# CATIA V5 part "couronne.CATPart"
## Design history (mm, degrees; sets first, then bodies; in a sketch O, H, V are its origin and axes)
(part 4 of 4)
    point P2044 (31.6793, -36.3337)
    point P2045 (31.9191, -36.4708)
    point P2046 (31.9191, -36.4708)
    point P2047 (32.1734, -36.6103)
    point P2048 (32.1734, -36.6103)
    point P2049 (32.4425, -36.7519)
    point P2050 (32.4425, -36.7519)
    point P2051 (32.7264, -36.895)
    point P2052 (32.7264, -36.895)
    point P2053 (33.0253, -37.0391)
    point P2054 (33.0253, -37.0391)
    point P2055 (33.3393, -37.1839)
    point P2056 (33.3393, -37.1839)
    point P2057 (33.4796, -37.2456)
    point P2058 (33.4796, -37.2456)
    point P2059 (33.4958, -37.2509)
    point P2060 (33.4958, -37.2509)
    point P2061 (33.5874, -37.2626)
    point P2062 (33.5874, -37.2626)
    point P2063 (33.8133, -37.2056)
    point P2064 (33.8133, -37.2056)
    point P2069 (34.1759, -36.8016)
    point P2070 (34.1759, -36.8016)
    point P2071 (34.1938, -36.6479)
    point P2072 (34.1938, -36.6479)
    point P2073 (34.1867, -36.6005)
    point P2074 (34.1867, -36.6005)
    point P2075 (34.179, -36.5767)
    point P2076 (34.179, -36.5767)
    point P2077 (34.0784, -36.2886)
    point P2078 (34.0784, -36.2886)
    point P2079 (33.9611, -35.9708)
    point P2080 (33.9611, -35.9708)
    point P2081 (33.8434, -35.6679)
    point P2082 (33.8434, -35.6679)
    point P2083 (33.7256, -35.3801)
    point P2084 (33.7256, -35.3801)
    point P2085 (33.6083, -35.1072)
    point P2086 (33.6083, -35.1072)
    point P2087 (33.492, -34.849)
    point P2088 (33.492, -34.849)
    point P2089 (33.3772, -34.6055)
    point P2090 (33.3772, -34.6055)
    point P2091 (33.2643, -34.3765)
    point P2092 (33.2643, -34.3765)
    point P2093 (33.1537, -34.1618)
    point P2094 (33.1537, -34.1618)
    point P2095 (33.046, -33.9614)
    point P2096 (33.046, -33.9614)
    point P2101 (33.8665, -32.9934)
    point P2102 (33.8665, -32.9934)
    point P2103 (34.0598, -33.0995)
    point P2104 (34.0598, -33.0995)
    point P2105 (34.2674, -33.2087)
    point P2106 (34.2674, -33.2087)
    point P2107 (34.4892, -33.3205)
    point P2108 (34.4892, -33.3205)
    point P2109 (34.7254, -33.4344)
    point P2110 (34.7254, -33.4344)
    point P2111 (34.9762, -33.55)
    point P2112 (34.9762, -33.55)
    point P2113 (35.2418, -33.6669)
    point P2114 (35.2418, -33.6669)
    point P2115 (35.5222, -33.7845)
    point P2116 (35.5222, -33.7845)
    point P2117 (35.8175, -33.9023)
    point P2118 (35.8175, -33.9023)
    point P2119 (36.1278, -34.0199)
    point P2120 (36.1278, -34.0199)
    point P2121 (36.4532, -34.1367)
    point P2122 (36.4532, -34.1367)
    point P2123 (36.5984, -34.186)
    point P2124 (36.5984, -34.186)
    point P2125 (36.6149, -34.1898)
    point P2126 (36.6149, -34.1898)
    point P2127 (36.7073, -34.1935)
    point P2128 (36.7073, -34.1935)
    point P2129 (36.9273, -34.117)
    point P2130 (36.9273, -34.117)
    point P2135 (37.2533, -33.6829)
    point P2136 (37.2533, -33.6829)
    point P2137 (37.2577, -33.5283)
    point P2138 (37.2577, -33.5283)
    point P2139 (37.2465, -33.4817)
    point P2140 (37.2465, -33.4817)
    point P2141 (37.2368, -33.4586)
    point P2142 (37.2368, -33.4586)
    point P2143 (37.1115, -33.1804)
    point P2144 (37.1115, -33.1804)
    point P2145 (36.967, -32.874)
    point P2146 (36.967, -32.874)
    point P2147 (36.8233, -32.5826)
    point P2148 (36.8233, -32.5826)
    point P2149 (36.6809, -32.3061)
    point P2150 (36.6809, -32.3061)
    point P2151 (36.5402, -32.0444)
    point P2152 (36.5402, -32.0444)
    point P2153 (36.4019, -31.7974)
    point P2154 (36.4019, -31.7974)
    point P2155 (36.2662, -31.5648)
    point P2156 (36.2662, -31.5648)
    point P2157 (36.1338, -31.3465)
    point P2158 (36.1338, -31.3465)
    point P2159 (36.005, -31.1423)
    point P2160 (36.005, -31.1423)
    point P2161 (35.8802, -30.952)
    point P2162 (35.8802, -30.952)
    point P2167 (36.6132, -29.9162)
    point P2168 (36.6132, -29.9162)
    point P2169 (36.815, -30.005)
    point P2170 (36.815, -30.005)
    point P2171 (37.0313, -30.0957)
    point P2172 (37.0313, -30.0957)
    point P2173 (37.262, -30.1877)
    point P2174 (37.262, -30.1877)
    point P2175 (37.5073, -30.2807)
    point P2176 (37.5073, -30.2807)
    point P2177 (37.7672, -30.374)
    point P2178 (37.7672, -30.374)
    point P2179 (38.0419, -30.4673)
    point P2180 (38.0419, -30.4673)
    point P2181 (38.3315, -30.5599)
    point P2182 (38.3315, -30.5599)
    point P2183 (38.636, -30.6516)
    point P2184 (38.636, -30.6516)
    point P2185 (38.9553, -30.7417)
    point P2186 (38.9553, -30.7417)
    point P2187 (39.2897, -30.8297)
    point P2188 (39.2897, -30.8297)
    point P2189 (39.4386, -30.8661)
    point P2190 (39.4386, -30.8661)
    point P2191 (39.4554, -30.8685)
    point P2192 (39.4554, -30.8685)
    point P2193 (39.5478, -30.8641)
    point P2194 (39.5478, -30.8641)
    point P2195 (39.7603, -30.7687)
    point P2196 (39.7603, -30.7687)
    point P2201 (40.0472, -30.3079)
    point P2202 (40.0472, -30.3079)
    point P2203 (40.0381, -30.1534)
    point P2204 (40.0381, -30.1534)
    point P2205 (40.0229, -30.108)
    point P2206 (40.0229, -30.108)
    point P2207 (40.0112, -30.0859)
    point P2208 (40.0112, -30.0859)
    point P2209 (39.8621, -29.8197)
    point P2210 (39.8621, -29.8197)
    point P2211 (39.6914, -29.527)
    point P2212 (39.6914, -29.527)
    point P2213 (39.5229, -29.2492)
    point P2214 (39.5229, -29.2492)
    point P2215 (39.3569, -28.9862)
    point P2216 (39.3569, -28.9862)
    point P2217 (39.1941, -28.7378)
    point P2218 (39.1941, -28.7378)
    point P2219 (39.0347, -28.5037)
    point P2220 (39.0347, -28.5037)
    point P2221 (38.8793, -28.2838)
    point P2222 (38.8793, -28.2838)
    point P2223 (38.7283, -28.0779)
    point P2224 (38.7283, -28.0779)
    point P2225 (38.5822, -27.8857)
    point P2226 (38.5822, -27.8857)
    point P2227 (38.4413, -27.7071)
    point P2228 (38.4413, -27.7071)
    point P2233 (39.0812, -26.6113)
    point P2234 (39.0812, -26.6113)
    point P2235 (39.2901, -26.6822)
    point P2236 (39.2901, -26.6822)
    point P2237 (39.5134, -26.7537)
    point P2238 (39.5134, -26.7537)
    point P2239 (39.7512, -26.8253)
    point P2240 (39.7512, -26.8253)
    point P2241 (40.0037, -26.8965)
    point P2242 (40.0037, -26.8965)
    point P2243 (40.2708, -26.9668)
    point P2244 (40.2708, -26.9668)
    point P2245 (40.5526, -27.0357)
    point P2246 (40.5526, -27.0357)
    point P2247 (40.8491, -27.1028)
    point P2248 (40.8491, -27.1028)
    point P2249 (41.1604, -27.1676)
    point P2250 (41.1604, -27.1676)
    point P2251 (41.4864, -27.2295)
    point P2252 (41.4864, -27.2295)
    point P2253 (41.8272, -27.288)
    point P2254 (41.8272, -27.288)
    point P2255 (41.9787, -27.3114)
    point P2256 (41.9787, -27.3114)
    point P2257 (41.9957, -27.3122)
    point P2258 (41.9957, -27.3122)
    point P2259 (42.0873, -27.2999)
    point P2260 (42.0873, -27.2999)
    point P2261 (42.2906, -27.1863)
    point P2262 (42.2906, -27.1863)
    point P2267 (42.5363, -26.7022)
    point P2268 (42.5363, -26.7022)
    point P2269 (42.5138, -26.5491)
    point P2270 (42.5138, -26.5491)
    point P2271 (42.4947, -26.5052)
    point P2272 (42.4947, -26.5052)
    point P2273 (42.4811, -26.4842)
    point P2274 (42.4811, -26.4842)
    point P2275 (42.3094, -26.232)
    point P2276 (42.3094, -26.232)
    point P2277 (42.1138, -25.9553)
    point P2278 (42.1138, -25.9553)
    point P2279 (41.9217, -25.6933)
    point P2280 (41.9217, -25.6933)
    point P2281 (41.7335, -25.4457)
    point P2282 (41.7335, -25.4457)
    point P2283 (41.5496, -25.2124)
    point P2284 (41.5496, -25.2124)
    point P2285 (41.3704, -24.9932)
    point P2286 (41.3704, -24.9932)
    point P2287 (41.1964, -24.7877)
    point P2288 (41.1964, -24.7877)
    point P2289 (41.0281, -24.5957)
    point P2290 (41.0281, -24.5957)
    point P2291 (40.8658, -24.417)
    point P2292 (40.8658, -24.417)
    point P2293 (40.7099, -24.2513)
    point P2294 (40.7099, -24.2513)
    point P2299 (41.2518, -23.1039)
    point P2300 (41.2518, -23.1039)
    point P2301 (41.4661, -23.1563)
    point P2302 (41.4661, -23.1563)
    point P2303 (41.6948, -23.2081)
    point P2304 (41.6948, -23.2081)
    point P2305 (41.9379, -23.2586)
    point P2306 (41.9379, -23.2586)
    point P2307 (42.1956, -23.3076)
    point P2308 (42.1956, -23.3076)
    point P2309 (42.4678, -23.3543)
    point P2310 (42.4678, -23.3543)
    point P2311 (42.7546, -23.3985)
    point P2312 (42.7546, -23.3985)
    point P2313 (43.0558, -23.4395)
    point P2314 (43.0558, -23.4395)
    point P2315 (43.3716, -23.4768)
    point P2316 (43.3716, -23.4768)
    point P2317 (43.7018, -23.5101)
    point P2318 (43.7018, -23.5101)
    point P2319 (44.0463, -23.5387)
    point P2320 (44.0463, -23.5387)
    point P2321 (44.1993, -23.5487)
    point P2322 (44.1993, -23.5487)
    point P2323 (44.2163, -23.5481)
    point P2324 (44.2163, -23.5481)
    point P2325 (44.3064, -23.5278)
    point P2326 (44.3064, -23.5278)
    point P2327 (44.4992, -23.397)
    point P2328 (44.4992, -23.397)
    point P2329 (44.5566, -23.3139)
    point P2330 (44.5566, -23.3139)
    point P2333 (44.7017, -22.8933)
    point P2334 (44.7017, -22.8933)
    point P2335 (44.666, -22.7428)
    point P2336 (44.666, -22.7428)
    point P2337 (44.6431, -22.7007)
    point P2338 (44.6431, -22.7007)
    point P2339 (44.6277, -22.6809)
    point P2340 (44.6277, -22.6809)
    point P2341 (44.4347, -22.4447)
    point P2342 (44.4347, -22.4447)
    point P2343 (44.2157, -22.1861)
    point P2344 (44.2157, -22.1861)
    point P2345 (44.0015, -21.9418)
    point P2346 (44.0015, -21.9418)
    point P2347 (43.7924, -21.7116)
    point P2348 (43.7924, -21.7116)
    point P2349 (43.5889, -21.4952)
    point P2350 (43.5889, -21.4952)
    point P2351 (43.3913, -21.2924)
    point P2352 (43.3913, -21.2924)
    point P2353 (43.2001, -21.1028)
    point P2354 (43.2001, -21.1028)
    point P2355 (43.0156, -20.9263)
    point P2356 (43.0156, -20.9263)
    point P2357 (42.8383, -20.7624)
    point P2358 (42.8383, -20.7624)
    point P2359 (42.6686, -20.6109)
    point P2360 (42.6686, -20.6109)
    point P2363 (43.0768, -19.4152)
    point P2364 (43.0768, -19.4152)
    point P2365 (43.1085, -19.4206)
    point P2366 (43.1085, -19.4206)
    point P2367 (43.3265, -19.4542)
    point P2368 (43.3265, -19.4542)
    point P2369 (43.5588, -19.4858)
    point P2370 (43.5588, -19.4858)
    point P2371 (43.8055, -19.515)
    point P2372 (43.8055, -19.515)
    point P2373 (44.0664, -19.5413)
    point P2374 (44.0664, -19.5413)
    point P2375 (44.3417, -19.5642)
    point P2376 (44.3417, -19.5642)
    point P2377 (44.6312, -19.5831)
    line L829 (-62.9973, -0.5786) -> (-47.248, -0.434)
    reference projected line E1 (-12.4995, -0.1148) -> (-68.4352, -0.6286) from DatumCurve1
    line L830 (62.9973, 0.5786) -> (47.248, 0.434)
    reference projected line E2 (65.9972, 0.6062) -> (12.4995, 0.1148) from edge of DatumCurve2
    coincidence: E1 L829, L830 E2, P2 P2377, P3 P4, P5 P6, P7 P8, P9 P10, P11 P12, P13 P14, P15 P16, P17 P18, P23 P24, P25 P26, P27 P28, P29 P30, P31 P32, P33 P34, P35 P36, P37 P38, P39 P40, P41 P42, P43 P44, P45 P46, P47 P48, P49 P50, P55 P56, P57 P58, P59 P60, P61 P62, P63 P64, P65 P66, P67 P68, P69 P70, P71 P72, P73 P74, P75 P76, P77 P78, P79 P80, P81 P82, P83 P84, P89 P90, P91 P92, P93 P94, P95 P96, P97 P98, P99 P100, P101 P102, P103 P104, P105 P106, P107 P108, P109 P110, P111 P112, P113 P114, P115 P116, P121 P122, P123 P124, P125 P126, P127 P128, P129 P130, P131 P132, P133 P134, P135 P136, P137 P138, P139 P140, P141 P142, P143 P144, P145 P146, P147 P148, P149 P150, P155 P156, P157 P158, P159 P160, P161 P162, P163 P164, P165 P166, P167 P168, P169 P170, P171 P172, P173 P174, P175 P176, P177 P178, P179 P180, P181 P182, P187 P188, P189 P190, P191 P192, P193 P194, P195 P196, P197 P198, P199 P200, P201 P202, P203 P204, P205 P206, P207 P208, P209 P210, P211 P212, P213 P214, P215 P216, P221 P222, P223 P224, P225 P226, P227 P228, P229 P230, P231 P232, P233 P234, P235 P236, P237 P238, P239 P240, P241 P242, P243 P244, P245 P246, P247 P248, P253 P254, P255 P256, P257 P258, P259 P260, P261 P262, P263 P264, P265 P266, P267 P268, P269 P270, P271 P272, P273 P274, P275 P276, P277 P278, P279 P280, P281 P282, P287 P288, P289 P290, P291 P292, P293 P294, P295 P296, P297 P298, P299 P300, P301 P302, P303 P304, P305 P306, P307 P308, P309 P310, P311 P312, P313 P314, P319 P320, P321 P322, P323 P324, P325 P326, P327 P328, P329 P330, P331 P332, P333 P334, P335 P336, P337 P338, P339 P340, P341 P342, P343 P344, P345 P346, P347 P348, P353 P354, P355 P356, P357 P358, P359 P360, P361 P362, P363 P364, P365 P366, P367 P368, P369 P370, P371 P372, P373 P374, P375 P376, P377 P378, P379 P380, P385 P386, P387 P388, P389 P390, P391 P392, P393 P394, P395 P396, P397 P398, P399 P400, P401 P402, P403 P404, P405 P406, P407 P408, P409 P410, P411 P412, P413 P414, P419 P420, P421 P422, P423 P424, P425 P426, P427 P428, P429 P430, P431 P432, P433 P434, P435 P436, P437 P438, P439 P440, P441 P442, P443 P444, P445 P446, P451 P452, P453 P454, P455 P456, P457 P458, P459 P460, P461 P462, P463 P464, P465 P466, P467 P468, P469 P470, P471 P472, P473 P474, P475 P476, P477 P478, P479 P480, P485 P486, P487 P488, P489 P490, P491 P492, P493 P494, P495 P496, P497 P498, P499 P500, P501 P502, P503 P504, P505 P506, P507 P508, P509 P510, P511 P512, P517 P518, P519 P520, P521 P522, P523 P524, P525 P526, P527 P528, P529 P530, P531 P532, P533 P534, P535 P536, P537 P538, P539 P540, P541 P542, P543 P544, P545 P546, P551 P552, P553 P554, P555 P556, P557 P558, P559 P560, P561 P562, P563 P564, P565 P566, P567 P568, P569 P570, P571 P572, P573 P574, P575 P576, P577 P578, P583 P584, P585 P586, P587 P588, P589 P590, P591 P592, P593 P594, P595 P596, P597 P598, P599 P600, P601 P602, P603 P604, P605 P606, P607 P608, P609 P610, P611 P612, P617 P618, P619 P620, P621 P622, P623 P624, P625 P626, P627 P628, P629 P630, P631 P632, P633 P634, P635 P636, P637 P638, P639 P640, P641 P642, P643 P644, P649 P650, P651 P652, P653 P654, P655 P656, P657 P658, P659 P660, P661 P662, P663 P664, P665 P666, P667 P668, P669 P670, P671 P672, P673 P674, P675 P676, P677 P678, P683 P684, P685 P686, P687 P688, P689 P690, P691 P692, P693 P694, P695 P696, P697 P698, P699 P700, P701 P702, P703 P704, P705 P706, P707 P708, P709 P710, P715 P716, P717 P718, P719 P720, P721 P722, P723 P724, P725 P726, P727 P728, P729 P730, P731 P732, P733 P734, P735 P736, P737 P738, P739 P740, P741 P742, P743 P744, P749 P750, P751 P752, P753 P754, P755 P756, P757 P758, P759 P760, P761 P762, P763 P764, P765 P766, P767 P768, P769 P770, P771 P772, P773 P774, P775 P776, P781 P782, P783 P784, P785 P786, P787 P788, P789 P790, P791 P792, P793 P794, P795 P796, P797 P798, P799 P800, P801 P802, P803 P804, P805 P806, P807 P808, P809 P810, P815 P816, P817 P818, P819 P820, P821 P822, P823 P824, P825 P826, P827 P828, P829 P830, P831 P832, P833 P834, P835 P836, P837 P838, P839 P840, P841 P842, P847 P848, P849 P850, P851 P852, P853 P854, P855 P856, P857 P858, P859 P860, P861 P862, P863 P864, P865 P866, P867 P868, P869 P870, P871 P872, P873 P874, P875 P876, P881 P882, P883 P884, P885 P886, P887 P888, P889 P890, P891 P892, P893 P894, P895 P896, P897 P898, P899 P900, P901 P902, P903 P904, P905 P906, P907 P908, P913 P914, P915 P916, P917 P918, P919 P920, P921 P922, P923 P924, P925 P926, P927 P928, P929 P930, P931 P932, P933 P934, P935 P936, P937 P938, P939 P940, P941 P942, P947 P948, P949 P950, P951 P952, P953 P954, P955 P956, P957 P958, P959 P960, P961 P962, P963 P964, P965 P966, P967 P968, P969 P970, P971 P972, P973 P974, P979 P980, P981 P982, P983 P984, P985 P986, P987 P988, P989 P990, P991 P992, P993 P994, P995 P996, P997 P998, P999 P1000, P1001 P1002, P1003 P1004, P1005 P1006, P1007 P1008, P1011 P1012, P1013 P1014, P1015 P1016, P1017 P1018, P1019 P1020, P1021 P1022, P1023 P1024, P1025 P1026, P1027 P1028, P1029 P1030, P1031 P1032, P1033 P1034, P1035 P1036, P1037 P1038, P1039 P1040, P1045 P1046, P1047 P1048, P1049 P1050, P1051 P1052, P1053 P1054, P1055 P1056, P1057 P1058, P1059 P1060, P1061 P1062, P1063 P1064, P1065 P1066, P1067 P1068, P1069 P1070, P1071 P1072, P1073 P1074, P1079 P1080, P1081 P1082, P1083 P1084, P1085 P1086, P1087 P1088, P1089 P1090, P1091 P1092, P1093 P1094, P1095 P1096, P1097 P1098, P1099 P1100, P1101 P1102, P1103 P1104, P1105 P1106, P1111 P1112, P1113 P1114, P1115 P1116, P1117 P1118, P1119 P1120, P1121 P1122, P1123 P1124, P1125 P1126, P1127 P1128, P1129 P1130, P1131 P1132, P1133 P1134, P1135 P1136, P1137 P1138, P1139 P1140, P1145 P1146, P1147 P1148, P1149 P1150, P1151 P1152, P1153 P1154, P1155 P1156, P1157 P1158, P1159 P1160, P1161 P1162, P1163 P1164, P1165 P1166, P1167 P1168, P1169 P1170, P1171 P1172, P1173 P1174, P1177 P1178, P1179 P1180, P1181 P1182, P1183 P1184, P1185 P1186, P1187 P1188, P1189 P1190, P1191 P1192, P1193 P1194, P1195 P1196, P1197 P1198, P1199 P1200, P1201 P1202, P1203 P1204, P1205 P1206, P1211 P1212, P1213 P1214, P1215 P1216, P1217 P1218, P1219 P1220, P1221 P1222, P1223 P1224, P1225 P1226, P1227 P1228, P1229 P1230, P1231 P1232, P1233 P1234, P1235 P1236, P1237 P1238, P1243 P1244, P1245 P1246, P1247 P1248, P1249 P1250, P1251 P1252, P1253 P1254, P1255 P1256, P1257 P1258, P1259 P1260, P1261 P1262, P1263 P1264, P1265 P1266, P1267 P1268, P1269 P1270, P1271 P1272, P1277 P1278, P1279 P1280, P1281 P1282, P1283 P1284, P1285 P1286, P1287 P1288, P1289 P1290, P1291 P1292, P1293 P1294, P1295 P1296, P1297 P1298, P1299 P1300, P1301 P1302, P1303 P1304, P1309 P1310, P1311 P1312, P1313 P1314, P1315 P1316, P1317 P1318, P1319 P1320, P1321 P1322, P1323 P1324, P1325 P1326, P1327 P1328, P1329 P1330, P1331 P1332, P1333 P1334, P1335 P1336, P1337 P1338, P1343 P1344, P1345 P1346, P1347 P1348, P1349 P1350, P1351 P1352, P1353 P1354, P1355 P1356, P1357 P1358, P1359 P1360, P1361 P1362, P1363 P1364, P1365 P1366, P1367 P1368, P1369 P1370, P1375 P1376, P1377 P1378, P1379 P1380, P1381 P1382, P1383 P1384, P1385 P1386, P1387 P1388, P1389 P1390, P1391 P1392, P1393 P1394, P1395 P1396, P1397 P1398, P1399 P1400, P1401 P1402, P1403 P1404, P1409 P1410, P1411 P1412, P1413 P1414, P1415 P1416, P1417 P1418, P1419 P1420, P1421 P1422, P1423 P1424, P1425 P1426, P1427 P1428, P1429 P1430, P1431 P1432, P1433 P1434, P1435 P1436, P1441 P1442, P1443 P1444, P1445 P1446, P1447 P1448, P1449 P1450, P1451 P1452, P1453 P1454, P1455 P1456, P1457 P1458, P1459 P1460, P1461 P1462, P1463 P1464, P1465 P1466, P1467 P1468, P1469 P1470, P1471 P1472, P1475 P1476, P1477 P1478, P1479 P1480, P1481 P1482, P1483 P1484, P1485 P1486, P1487 P1488, P1489 P1490, P1491 P1492, P1493 P1494, P1495 P1496, P1497 P1498, P1499 P1500, P1501 P1502, P1507 P1508, P1509 P1510, P1511 P1512, P1513 P1514, P1515 P1516, P1517 P1518, P1519 P1520, P1521 P1522, P1523 P1524, P1525 P1526, P1527 P1528, P1529 P1530, P1531 P1532, P1533 P1534, P1535 P1536, P1541 P1542, P1543 P1544, P1545 P1546, P1547 P1548, P1549 P1550, P1551 P1552, P1553 P1554, P1555 P1556, P1557 P1558, P1559 P1560, P1561 P1562, P1563 P1564, P1565 P1566, P1567 P1568, P1573 P1574, P1575 P1576, P1577 P1578, P1579 P1580, P1581 P1582, P1583 P1584, P1585 P1586, P1587 P1588, P1589 P1590, P1591 P1592, P1593 P1594, P1595 P1596, P1597 P1598, P1599 P1600, P1601 P1602, P1607 P1608, P1609 P1610, P1611 P1612, P1613 P1614, P1615 P1616, P1617 P1618, P1619 P1620, P1621 P1622, P1623 P1624, P1625 P1626, P1627 P1628, P1629 P1630, P1631 P1632, P1633 P1634, P1639 P1640, P1641 P1642, P1643 P1644, P1645 P1646, P1647 P1648, P1649 P1650, P1651 P1652, P1653 P1654, P1655 P1656, P1657 P1658, P1659 P1660, P1661 P1662, P1663 P1664, P1665 P1666, P1667 P1668, P1673 P1674, P1675 P1676, P1677 P1678, P1679 P1680, P1681 P1682, P1683 P1684, P1685 P1686, P1687 P1688, P1689 P1690, P1691 P1692, P1693 P1694, P1695 P1696, P1697 P1698, P1699 P1700, P1705 P1706, P1707 P1708, P1709 P1710, P1711 P1712, P1713 P1714, P1715 P1716, P1717 P1718, P1719 P1720, P1721 P1722, P1723 P1724, P1725 P1726, P1727 P1728, P1729 P1730, P1731 P1732, P1733 P1734, P1739 P1740, P1741 P1742, P1743 P1744, P1745 P1746, P1747 P1748, P1749 P1750, P1751 P1752, P1753 P1754, P1755 P1756, P1757 P1758, P1759 P1760, P1761 P1762, P1763 P1764, P1765 P1766, P1771 P1772, P1773 P1774, P1775 P1776, P1777 P1778, P1779 P1780, P1781 P1782, P1783 P1784, P1785 P1786, P1787 P1788, P1789 P1790, P1791 P1792, P1793 P1794, P1795 P1796, P1797 P1798, P1799 P1800, P1805 P1806, P1807 P1808, P1809 P1810, P1811 P1812, P1813 P1814, P1815 P1816, P1817 P1818, P1819 P1820, P1821 P1822, P1823 P1824, P1825 P1826, P1827 P1828, P1829 P1830, P1831 P1832, P1837 P1838, P1839 P1840, P1841 P1842, P1843 P1844, P1845 P1846, P1847 P1848, P1849 P1850, P1851 P1852, P1853 P1854, P1855 P1856, P1857 P1858, P1859 P1860, P1861 P1862, P1863 P1864, P1865 P1866, P1869 P1870, P1871 P1872, P1873 P1874, P1875 P1876, P1877 P1878, P1879 P1880, P1881 P1882, P1883 P1884, P1885 P1886, P1887 P1888, P1889 P1890, P1891 P1892, P1893 P1894, P1895 P1896, P1897 P1898, P1903 P1904, P1905 P1906, P1907 P1908, P1909 P1910, P1911 P1912, P1913 P1914, P1915 P1916, P1917 P1918, P1919 P1920, P1921 P1922, P1923 P1924, P1925 P1926, P1927 P1928, P1929 P1930, P1931 P1932, P1937 P1938, P1939 P1940, P1941 P1942, P1943 P1944, P1945 P1946, P1947 P1948, P1949 P1950, P1951 P1952, P1953 P1954, P1955 P1956, P1957 P1958, P1959 P1960, P1961 P1962, P1963 P1964, P1969 P1970, P1971 P1972, P1973 P1974, P1975 P1976, P1977 P1978, P1979 P1980, P1981 P1982, P1983 P1984, P1985 P1986, P1987 P1988, P1989 P1990, P1991 P1992, P1993 P1994, P1995 P1996, P1997 P1998, P2003 P2004, P2005 P2006, P2007 P2008, P2009 P2010, P2011 P2012, P2013 P2014, P2015 P2016, P2017 P2018, P2019 P2020, P2021 P2022, P2023 P2024, P2025 P2026, P2027 P2028, P2029 P2030, P2031 P2032, P2035 P2036, P2037 P2038, P2039 P2040, P2041 P2042, P2043 P2044, P2045 P2046, P2047 P2048, P2049 P2050, P2051 P2052, P2053 P2054, P2055 P2056, P2057 P2058, P2059 P2060, P2061 P2062, P2063 P2064, P2069 P2070, P2071 P2072, P2073 P2074, P2075 P2076, P2077 P2078, P2079 P2080, P2081 P2082, P2083 P2084, P2085 P2086, P2087 P2088, P2089 P2090, P2091 P2092, P2093 P2094, P2095 P2096, P2101 P2102, P2103 P2104, P2105 P2106, P2107 P2108, P2109 P2110, P2111 P2112, P2113 P2114, P2115 P2116, P2117 P2118, P2119 P2120, P2121 P2122, P2123 P2124, P2125 P2126, P2127 P2128, P2129 P2130, P2135 P2136, P2137 P2138, P2139 P2140, P2141 P2142, P2143 P2144, P2145 P2146, P2147 P2148, P2149 P2150, P2151 P2152, P2153 P2154, P2155 P2156, P2157 P2158, P2159 P2160, P2161 P2162, P2167 P2168, P2169 P2170, P2171 P2172, P2173 P2174, P2175 P2176, P2177 P2178, P2179 P2180, P2181 P2182, P2183 P2184, P2185 P2186, P2187 P2188, P2189 P2190, P2191 P2192, P2193 P2194, P2195 P2196, P2201 P2202, P2203 P2204, P2205 P2206, P2207 P2208, P2209 P2210, P2211 P2212, P2213 P2214, P2215 P2216, P2217 P2218, P2219 P2220, P2221 P2222, P2223 P2224, P2225 P2226, P2227 P2228, P2233 P2234, P2235 P2236, P2237 P2238, P2239 P2240, P2241 P2242, P2243 P2244, P2245 P2246, P2247 P2248, P2249 P2250, P2251 P2252, P2253 P2254, P2255 P2256, P2257 P2258, P2259 P2260, P2261 P2262, P2267 P2268, P2269 P2270, P2271 P2272, P2273 P2274, P2275 P2276, P2277 P2278, P2279 P2280, P2281 P2282, P2283 P2284, P2285 P2286, P2287 P2288, P2289 P2290, P2291 P2292, P2293 P2294, P2299 P2300, P2301 P2302, P2303 P2304, P2305 P2306, P2307 P2308, P2309 P2310, P2311 P2312, P2313 P2314, P2315 P2316, P2317 P2318, P2319 P2320, P2321 P2322, P2323 P2324, P2325 P2326, P2327 P2328, P2329 P2330, P2333 P2334, P2335 P2336, P2337 P2338, P2339 P2340, P2341 P2342, P2343 P2344, P2345 P2346, P2347 P2348, P2349 P2350, P2351 P2352, P2353 P2354, P2355 P2356, P2357 P2358, P2359 P2360, P2363 P2364, P2365 P2366, P2367 P2368, P2369 P2370, P2371 P2372, P2373 P2374, P2375 P2376
    fix: A362, A51, A50
  Pad1: profile Sketch1, direction (-1, 0, 0), length 15
  Sketch2 on Plane1, origin (43.8512, 0, 0), H (0, 1, 0), V (0, 0, 1)
    circle A1 centre (251.964, 88.354) radius 48.6
    reference projected circle E1 centre (251.964, 88.354) radius 48.6 from edge of DatumCurve3
    coincidence: A1 E1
